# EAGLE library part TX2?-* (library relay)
2 AMP. HIGH CAPACITY RELAY NAiS WITH HIGH SURGE VOLTAGE & HIGH BREAKDOWN VOLTAGE Source: http://www.mew-europe.com/.. en_ds_61022_0001.pdf
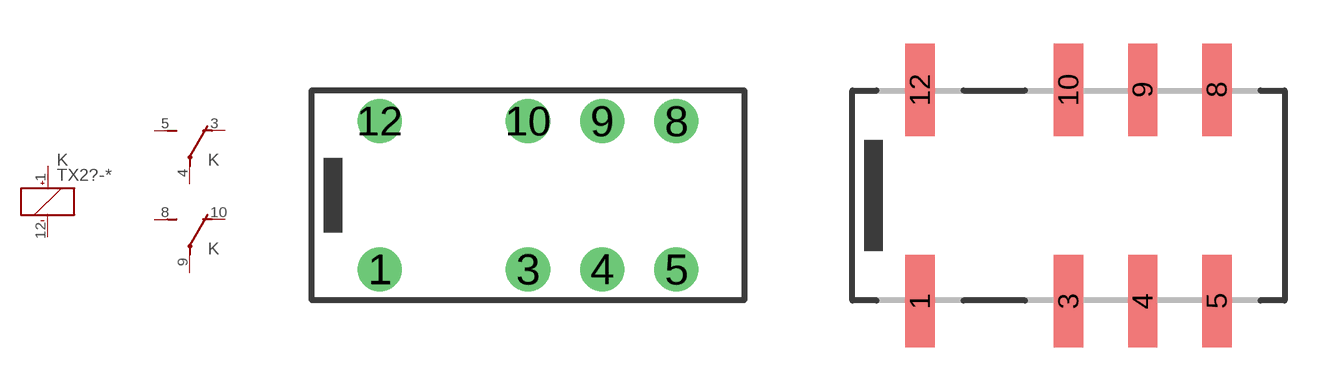
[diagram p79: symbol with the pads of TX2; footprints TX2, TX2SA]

Designator prefix K; gates _=K+- 1=U 2=U

## TX2-1.5V (MPN: TX2-1.5V; OC_FARNELL: unknown; OC_NEWARK: 13P9570), TX2-3V (MPN: TX2-3V; OC_FARNELL: unknown; OC_NEWARK: 13P9573), TX2-4.5V (MF: AROMAT/ MATSUSHITA; MPN: TX2-4.5V; OC_FARNELL: 1200950; OC_NEWARK: 64K3216), TX2-5V (MF: AROMAT/ MATSUSHITA; MPN: TX2-5V; OC_FARNELL: 1200950; OC_NEWARK: 67K1296), TX2-6V (MF: AROMAT/ MATSUSHITA; MPN: TX2-6V; OC_FARNELL: unknown; OC_NEWARK: 11C0387), TX2-9V (MF: AROMAT/ MATSUSHITA; MPN: TX2-9V; OC_FARNELL: unknown; OC_NEWARK: 11C0388), TX2-12V (MF: AROMAT/ MATSUSHITA; MPN: TX2-12V; OC_FARNELL: 1200952; OC_NEWARK: 67K1295), TX2-24V (MF: AROMAT/ MATSUSHITA; MPN: TX2-24V; OC_FARNELL: 1124059; OC_NEWARK: 64K3215)  [TX2]
1  _:+  pas
3  1:O  pas
4  1:P  pas
5  1:S  pas
8  2:S  pas
9  2:P  pas
10  2:O  pas
12  _:-  pas

## TX2SA-1.5V (OC_FARNELL: unknown; OC_NEWARK: unknown), TX2SA-3V (MPN: TX2SA-3V; OC_FARNELL: unknown; OC_NEWARK: 13P9584), TX2SA-4.5V (MF: AROMAT/ MATSUSHITA; MPN: TX2SA-4.5V; OC_FARNELL: unknown; OC_NEWARK: 92F1604), TX2SA-5V (MPN: TX2SA-5V; OC_FARNELL: 1200957; OC_NEWARK: 13P9589), TX2SA-6V (MPN: TX2SA-6V-X; OC_FARNELL: unknown; OC_NEWARK: 13P9592), TX2SA-9V (MPN: TX2SA-9V; OC_FARNELL: unknown; OC_NEWARK: 13P9593), TX2SA-12V (MF: AROMAT/ MATSUSHITA; MPN: TX2SA-12V; OC_FARNELL: 910480; OC_NEWARK: 64K3217), TX2SA-24V (MF: AROMAT/ MATSUSHITA; MPN: TX2SA-24V; OC_FARNELL: 1652603; OC_NEWARK: 64K3218), TX2SA-48V (OC_FARNELL: unknown; OC_NEWARK: unknown)  [TX2SA]
Pads as for TX2

## TX2-L-1.5V (OC_FARNELL: unknown; OC_NEWARK: unknown), TX2-L-3V (MPN: TX2-L-3V; OC_FARNELL: unknown; OC_NEWARK: 15P9975), TX2-L-4.5V (MPN: TX2-L-4.5V; OC_FARNELL: unknown; OC_NEWARK: 15P9976), TX2-L-5V (MPN: TX2-L-5V; OC_FARNELL: unknown; OC_NEWARK: 15P9977), TX2-L-6V (OC_FARNELL: unknown; OC_NEWARK: unknown), TX2-L-9V (MPN: TX2-L-9V; OC_FARNELL: unknown; OC_NEWARK: 15P9978), TX2-L-12V (MPN: TX2-L-12V; OC_FARNELL: unknown; OC_NEWARK: 11C0367), TX2-L-24V (MPN: TX2-L-24V-1; OC_FARNELL: unknown; OC_NEWARK: 12N3976)  [TX2]
1  _:-  pas
3  1:O  pas
4  1:P  pas
5  1:S  pas
8  2:S  pas
9  2:P  pas
10  2:O  pas
12  _:+  pas

## TX2SL-1.5V (OC_FARNELL: unknown; OC_NEWARK: unknown), TX2SL-3V (MPN: TX2SL-3V; OC_FARNELL: unknown; OC_NEWARK: 13P9598), TX2SL-4.5V (MPN: TX2SL-4.5V; OC_FARNELL: unknown; OC_NEWARK: 13P9600), TX2SL-5V (MPN: TX2SL-5V; OC_FARNELL: unknown; OC_NEWARK: 13P9603), TX2SL-6V (OC_FARNELL: unknown; OC_NEWARK: unknown), TX2SL-9V (MPN: TX2SL-9V-1; OC_FARNELL: unknown; OC_NEWARK: 11N6123), TX2SL-12V (MF: AROMAT/ MATSUSHITA; MPN: TX2SL-12V; OC_FARNELL: unknown; OC_NEWARK: 11C0519), TX2SL-24V (MPN: TX2SL-24V; OC_FARNELL: unknown; OC_NEWARK: 16P9442), TX2SL-48V (MPN: TX2SL-48V; OC_FARNELL: unknown; OC_NEWARK: 13P9602)  [TX2SL]
Pads as for TX2

## TX2SS-1.5V (OC_FARNELL: unknown; OC_NEWARK: unknown), TX2SS-3V (MPN: TX2SS-3V-Z; OC_FARNELL: unknown; OC_NEWARK: 13P9606), TX2SS-4.5V (MPN: TX2SS-4.5V; OC_FARNELL: unknown; OC_NEWARK: 13P9607), TX2SS-5V (MPN: TX2SS-5V; OC_FARNELL: unknown; OC_NEWARK: 13P9610), TX2SS-6V (OC_FARNELL: unknown; OC_NEWARK: unknown), TX2SS-9V (OC_FARNELL: unknown; OC_NEWARK: unknown), TX2SS-12V (OC_FARNELL: unknown; OC_NEWARK: unknown), TX2SS-24V (MPN: TX2SS-24V; OC_FARNELL: unknown; OC_NEWARK: 13P9605), TX2SS-48V (MPN: TX2SS-48V; OC_FARNELL: unknown; OC_NEWARK: 13P9609)  [TX2SS]
Pads as for TX2

## TX2SA-L-1.5V (OC_FARNELL: unknown; OC_NEWARK: unknown), TX2SA-L-3V (OC_FARNELL: unknown; OC_NEWARK: unknown), TX2SA-L-4.5V (OC_FARNELL: unknown; OC_NEWARK: unknown), TX2SA-L-5V (OC_FARNELL: unknown; OC_NEWARK: unknown), TX2SA-L-6V (OC_FARNELL: unknown; OC_NEWARK: unknown), TX2SA-L-9V (OC_FARNELL: unknown; OC_NEWARK: unknown), TX2SA-L-12V (OC_FARNELL: unknown; OC_NEWARK: unknown), TX2SA-L-24V (OC_FARNELL: unknown; OC_NEWARK: unknown)  [TX2SA]
Pads as for TX2

## TX2SL-L-1.5V (OC_FARNELL: unknown; OC_NEWARK: unknown), TX2SL-L-3V (MF: AROMAT/ MATSUSHITA; MPN: TX2SL-L-3V; OC_FARNELL: unknown; OC_NEWARK: 11C0477), TX2SL-L-4.5V (OC_FARNELL: unknown; OC_NEWARK: unknown), TX2SL-L-5V (OC_FARNELL: unknown; OC_NEWARK: unknown), TX2SL-L-6V (OC_FARNELL: unknown; OC_NEWARK: unknown), TX2SL-L-9V (OC_FARNELL: unknown; OC_NEWARK: unknown), TX2SL-L-12V (OC_FARNELL: unknown; OC_NEWARK: unknown), TX2SL-L-24V (MPN: TX2SL-L-24V-1; OC_FARNELL: unknown; OC_NEWARK: 12N3990)  [TX2SL]
Pads as for TX2

## TX2SS-L-1.5V (OC_FARNELL: unknown; OC_NEWARK: unknown), TX2SS-L-3V (MPN: TX2SS-L-3V-1; OC_FARNELL: unknown; OC_NEWARK: 12N3991), TX2SS-L-4.5V (OC_FARNELL: unknown; OC_NEWARK: unknown), TX2SS-L-5V (OC_FARNELL: unknown; OC_NEWARK: unknown), TX2SS-L-6V (OC_FARNELL: unknown; OC_NEWARK: unknown), TX2SS-L-9V (OC_FARNELL: unknown; OC_NEWARK: unknown), TX2SS-L-12V (MF: AROMAT/ MATSUSHITA; MPN: TX2SS-L-12V-Z; OC_FARNELL: unknown; OC_NEWARK: 11C0549), TX2SS-L-24V (OC_FARNELL: unknown; OC_NEWARK: unknown)  [TX2SS]
Pads as for TX2

## Footprint TX2 (pad centres in mm)
2 AMP. HIGH CAPACITY RELAY NAiS WITH HIGH SURGE VOLTAGE & HIGH BREAKDOWN VOLTAGE Source: http://www.mew-europe.com/.. en_ds_61022_0001.pdf
drill 1 round: 1 -5.08,-2.54; 3 0,-2.54; 4 2.54,-2.54; 5 5.08,-2.54; 8 5.08,2.54; 9 2.54,2.54; 10 0,2.54; 12 -5.08,2.54

## Footprint TX2SA (pad centres in mm)
2 AMP. HIGH CAPACITY RELAY NAiS WITH HIGH SURGE VOLTAGE & HIGH BREAKDOWN VOLTAGE Source: http://www.mew-europe.com/.. en_ds_61022_0001.pdf
smd 1 x 3.16: 1 -5.08,-3.62; 3 0,-3.62; 4 2.54,-3.62; 5 5.08,-3.62; 8 5.08,3.62; 9 2.54,3.62; 10 0,3.62; 12 -5.08,3.62

## Footprint TX2SL (pad centres in mm)
2 AMP. HIGH CAPACITY RELAY NAiS WITH HIGH SURGE VOLTAGE & HIGH BREAKDOWN VOLTAGE Source: http://www.mew-europe.com/.. en_ds_61022_0001.pdf
smd 1 x 3.16: 1 -5.08,-3.62; 3 0,-3.62; 4 2.54,-3.62; 5 5.08,-3.62; 8 5.08,3.62; 9 2.54,3.62; 10 0,3.62; 12 -5.08,3.62

## Footprint TX2SS (pad centres in mm)
2 AMP. HIGH CAPACITY RELAY NAiS WITH HIGH SURGE VOLTAGE & HIGH BREAKDOWN VOLTAGE Source: http://www.mew-europe.com/.. en_ds_61022_0001.pdf
smd 1 x 2.16: 1 -5.08,-3.12; 3 0,-3.12; 4 2.54,-3.12; 5 5.08,-3.12; 8 5.08,3.12; 9 2.54,3.12; 10 0,3.12; 12 -5.08,3.12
